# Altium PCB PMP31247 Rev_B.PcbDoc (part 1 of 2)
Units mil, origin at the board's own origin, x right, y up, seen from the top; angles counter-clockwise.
Board outline 3522.83 x 1490.94 mil, 4 copper layers (Top Layer, GND Plane, Signal Layer, Bottom Layer), stack 70.4 mil thick; 56 components, 24 nets, 121 pads, 112 vias.
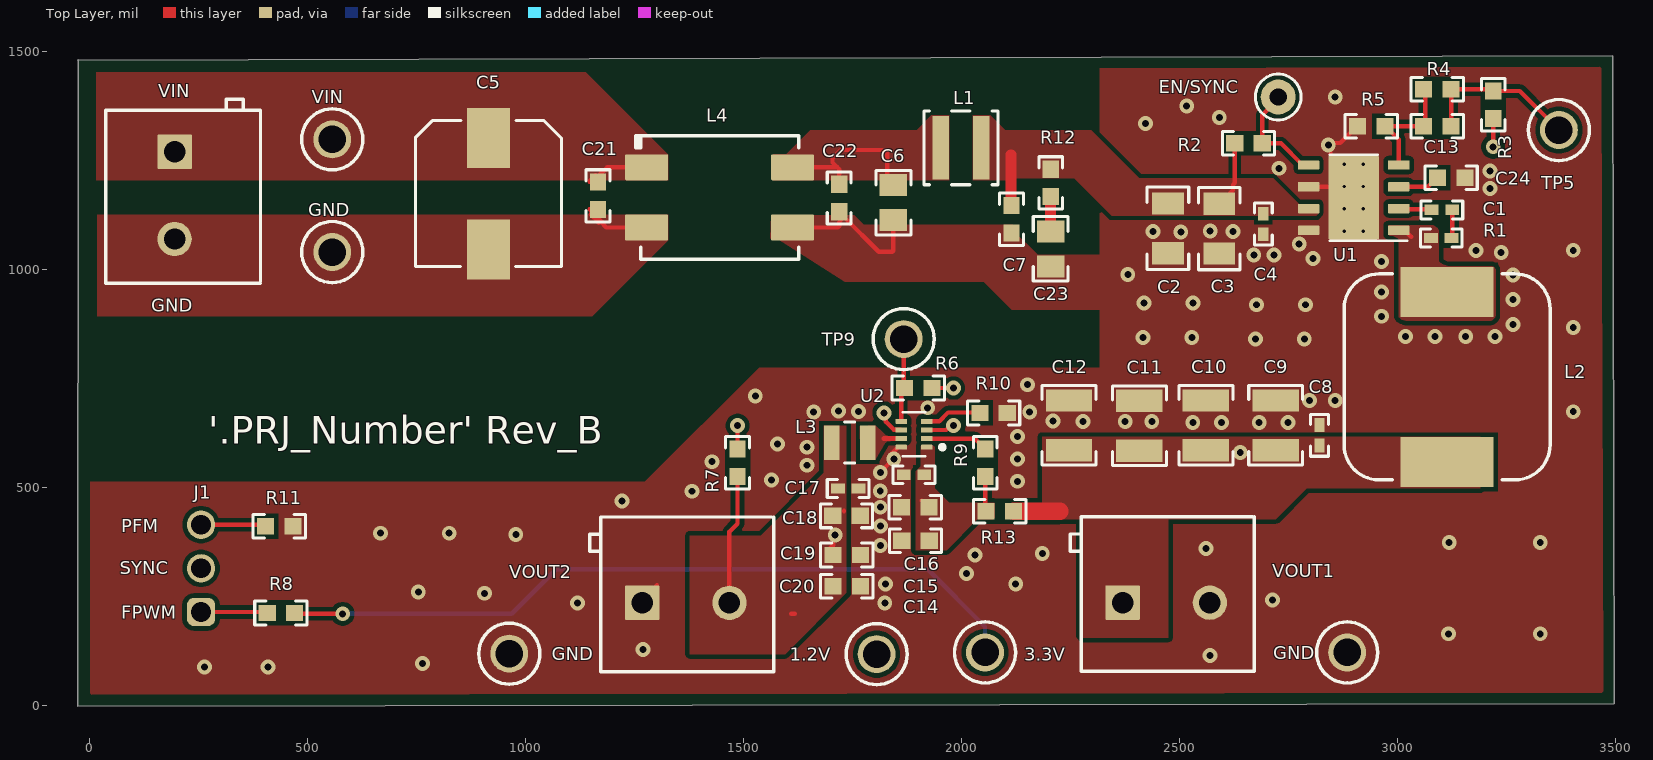
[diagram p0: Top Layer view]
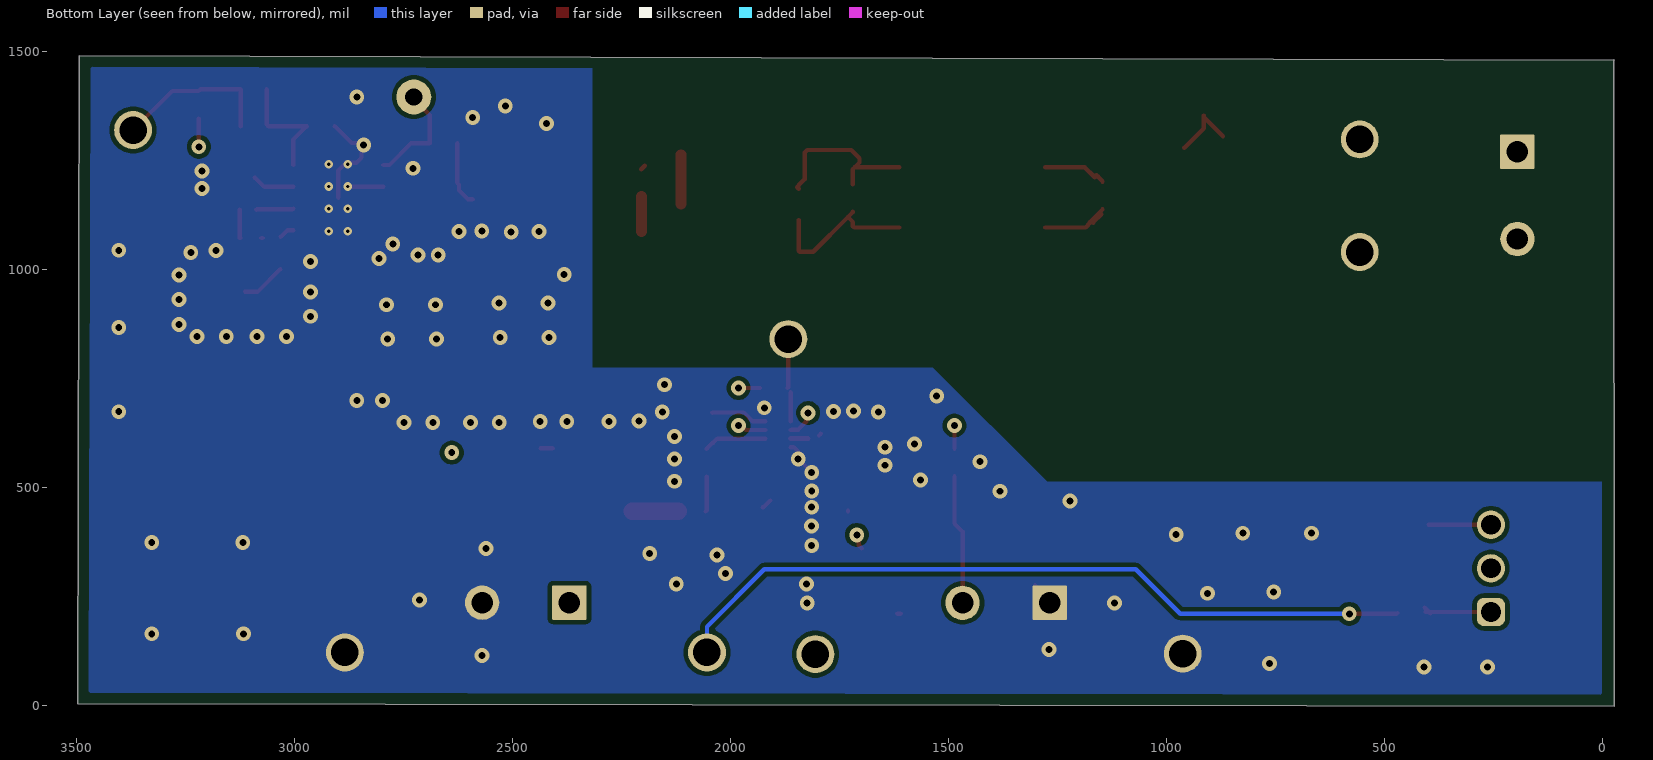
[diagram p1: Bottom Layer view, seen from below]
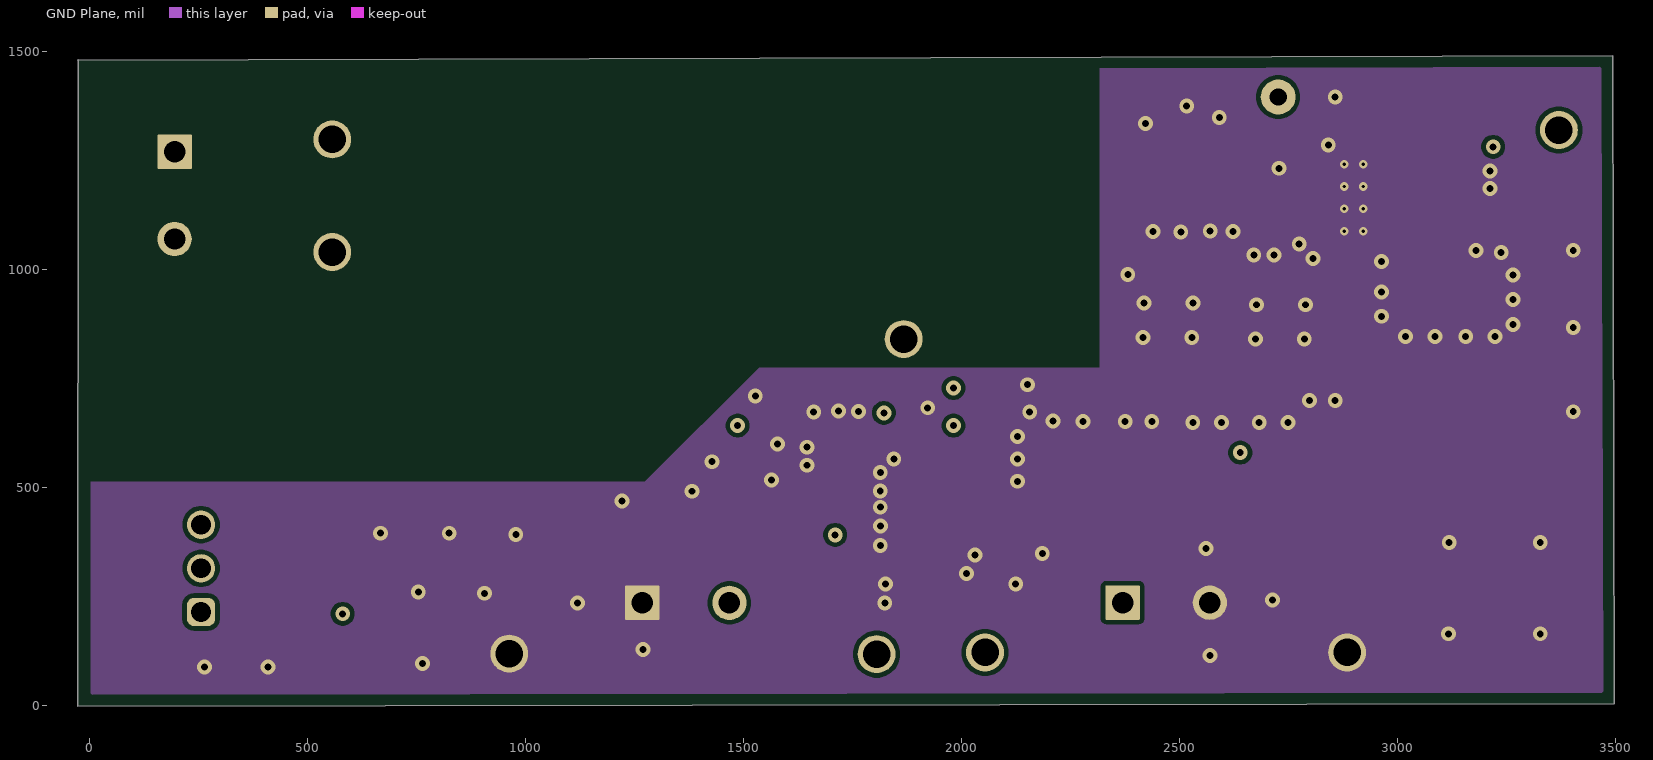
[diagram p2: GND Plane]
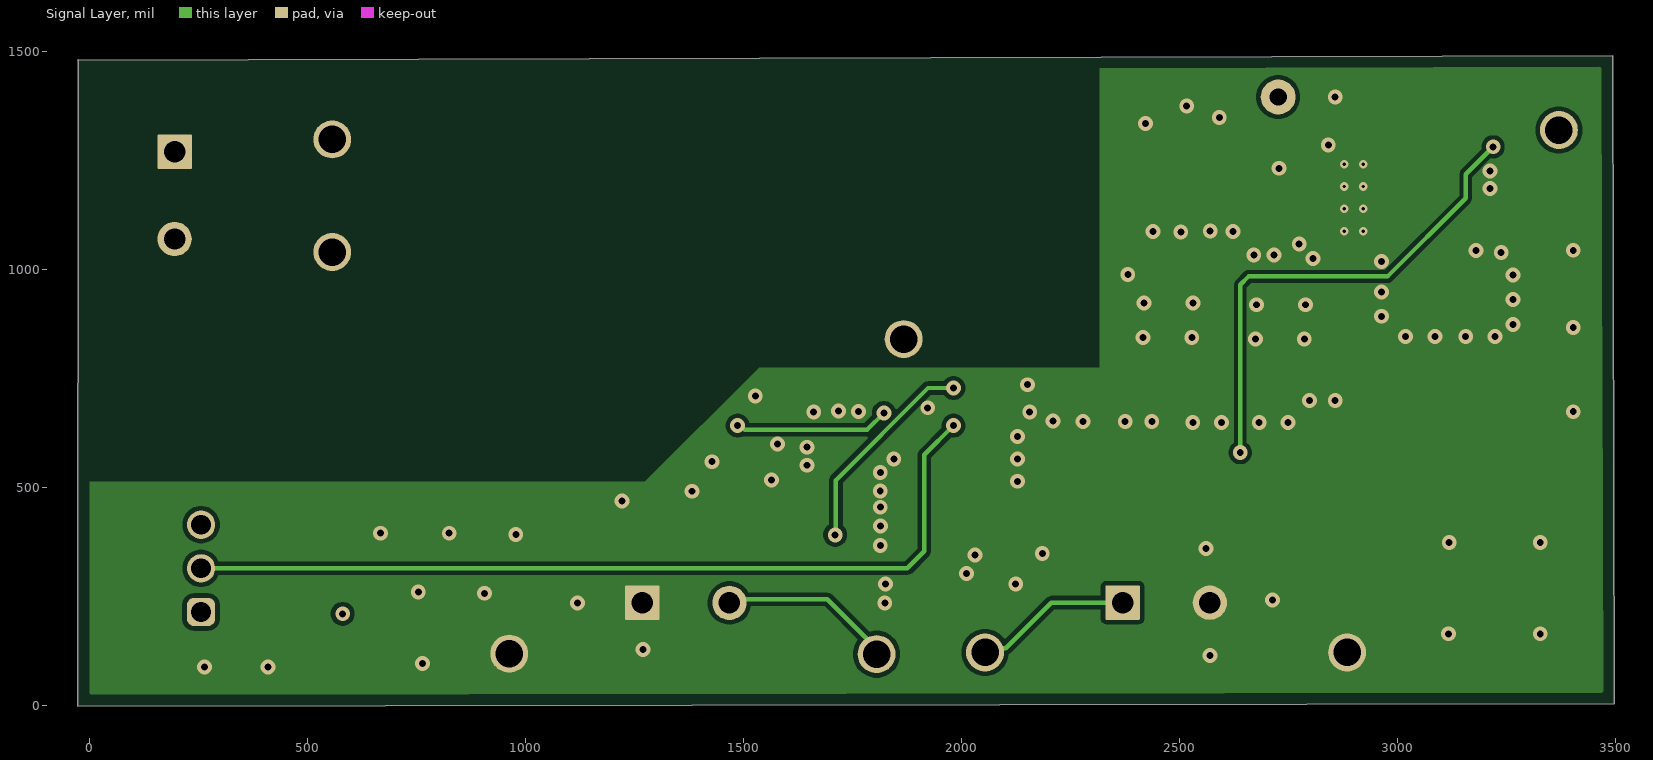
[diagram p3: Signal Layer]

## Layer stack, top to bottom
Top Solder: solder mask 0.4, Solder Resist, Dk 3.5
Top Layer: signal copper 1.4
Dielectric 1: prepreg 2.8, PP-006, Dk 4.1
GND Plane: signal copper 1.4
Dielectric1: dielectric 59.2, FR-4 High Tg, Dk 4.8
Signal Layer: signal copper 1.4
Dielectric 2: prepreg 2.8, PP-006, Dk 4.1
Bottom Layer: signal copper 1.4
Bottom Solder: solder mask 0.4, Solder Resist, Dk 3.5

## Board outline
-26.77,-0.79 -25.98,1481.5 -26.77,1479.92 3492.13,1490.16 3496.06,3.94

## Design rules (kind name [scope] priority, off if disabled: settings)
AcuteAngle [All] p1: minimum=4.50000000000000E+0001 checktracksonly=FALSE
AssemblyTestPointUsage [All] p1: valid=2
BoardOutlineClearance BoardOutlineClearance_MountingHoles [OnCopper and InComponentClass('Mounting Holes')] p1: gap=39.37 ignorepadtopadclearanceinfootprint=FALSE
BoardOutlineClearance BoardOutlineClearance_Poly [OnCopper and IsPoly] p2: gap=25 ignorepadtopadclearanceinfootprint=FALSE
BoardOutlineClearance [OnCopper and Not InComponentClass('Logo') and not InComponentClass('FiducialMark') and not InRegion(1000,500,4000,800) and not InPoly] p3: gap=40 ignorepadtopadclearanceinfootprint=FALSE
Clearance Clearance_Keepouts [((IsTrack Or IsArc) And Not InPoly) And IsFree and IsKeepOut vs ((IsTrack Or IsArc) And Not InPoly) And IsFree and IsKeepOut] p1: gap=0 ignorepadtopadclearanceinfootprint=FALSE
Clearance Clearance_Poly [InPolygon] p2: gap=10 ignorepadtopadclearanceinfootprint=TRUE
Clearance Clearance_FiducialMark [IsKeepOut and InComponentClass('FiducialMark') vs IsPad and InComponentClass('FiducialMark')] p3: gap=0 ignorepadtopadclearanceinfootprint=FALSE
Clearance [All] p4: gap=7.87 ignorepadtopadclearanceinfootprint=TRUE
ComponentClearance ComponentClearance_MountingHoles_FiducialMarks [InComponentClass('Mounting Holes') vs InComponentClass('FiducialMark')] p1: gap=50 collisioncheckmode=3 verticalgap=10 showdistances=FALSE
ComponentClearance ComponentClearance_Shunt [InComponentClass('Header') vs InComponentClass('Shunt')] p2: gap=0 collisioncheckmode=3 verticalgap=0 showdistances=FALSE
ComponentClearance ComponentClearance_Logo [InComponentClass('Logo')] p3: gap=30 collisioncheckmode=3 verticalgap=10 showdistances=FALSE
ComponentClearance ComponentClearance_ScrewToNut [(HasFootprint('NY PMS 440 0025 PH')) vs (HasFootprint('Keystone_1902C'))] p4: gap=5 collisioncheckmode=3 verticalgap=10 showdistances=FALSE
ComponentClearance ComponentClearance_MountingHoles [InComponentClass('Mounting Holes')] p5: gap=100 collisioncheckmode=3 verticalgap=100000 showdistances=FALSE
ComponentClearance ComponentClearance_SmallPassives [HasFootprint('0201*') or HasFootprint('0402*') or HasFootprint('0508') or HasFootprint('0603*') or HasFootprint('0612') or HasFootprint('0805*') or HasFootprint('0815*') or HasFootprint('0830*') or HasFootprint('1206*') or HasFootprint('1210*') or HasFootprint('1808*') or HasFootprint('1812*') or HasFootprint('1825*') or HasFootprint('2010*') or HasFootprint('2220*') or HasFootprint('2225*') or HasFootprint('2512*') or HasFootprint('2728*') or HasFootprint('3518*') vs HasFootprint('0201*') or HasFootprint('0402*') or HasFootprint('0508') or HasFootprint('0603*') or HasFootprint('0612') or HasFootprint('0805*') or HasFootprint('0815*') or HasFootprint('0830*') or HasFootprint('1206*') or HasFootprint('1210*') or HasFootprint('1808*') or HasFootprint('1812*') or HasFootprint('1825*') or HasFootprint('2010*') or HasFootprint('2220*') or HasFootprint('2225*') or HasFootprint('2512*') or HasFootprint('2728*') or HasFootprint('3518*')] p6: gap=14.96 collisioncheckmode=3 verticalgap=10 showdistances=FALSE
ComponentClearance ComponentClearance_THtoSMT [IsThruComponent vs IsSMTComponent] p7: gap=30 collisioncheckmode=3 verticalgap=30 showdistances=FALSE
ComponentClearance ComponentClearance_THtoTH [IsThruComponent vs IsThruComponent] p8: gap=20 collisioncheckmode=3 verticalgap=30 showdistances=FALSE
ComponentClearance [All] p9: gap=20 collisioncheckmode=3 verticalgap=10 showdistances=FALSE
DiffPairsRouting [All] p1: maxlimit=100 minlimit=10 mostfreqgap=10 toplayer_minwidth=15 toplayer_maxwidth=15 toplayer_prefwidth=15 midlayer1_minwidth=15 midlayer1_maxwidth=15 midlayer1_prefwidth=15 midlayer2_minwidth=15 midlayer2_maxwidth=15 midlayer2_prefwidth=15 bottomlayer_minwidth=15 bottomlayer_maxwidth=15 bottomlayer_prefwidth=15 maxuncoupledlength=1000
FabricationTestPointUsage TestPointUsage [All] p1: valid=2 allowmultiple=FALSE
FabricationTestpoint Testpoint [All] p1: side=3 testpointundercomponent=TRUE minsize=40 maxsize=100 preferedsize=60 minholesize=0 maxholesize=40 preferedholesize=32 testpointgrid=1 allowsidetop=TRUE allowsidebottom=TRUE usegrid=TRUE gridtolerance=0.01
FanoutControl Fanout_LCC [IsLCC] p1: bgadir=Out bgaviamode=Centered fanoutstyle=Auto fanoutdirection=Alternating viagrid=1 // Fanout_LCC (Default Rule)
FanoutControl Fanout_BGA [IsBGA] p2: bgadir=Out bgaviamode=Centered fanoutstyle=Auto fanoutdirection=Alternating viagrid=1 // Fanout_BGA (Default Rule)
FanoutControl Fanout_Default [All] p4: bgadir=Out bgaviamode=Centered fanoutstyle=Auto fanoutdirection=Alternating viagrid=1 // Fanout_Default (Default Rule)
FanoutControl Fanout_Small [(CompPinCount < 5)] p5: bgadir=Out bgaviamode=Centered fanoutstyle=Auto fanoutdirection=OutThenIn viagrid=1 // Fanout_Small (Default Rule)
HoleSize [All] p1: absolutevalues=TRUE maxlimit=251 minlimit=7.87 maxpercent=80.000 minpercent=20.000
MinimumAnnularRing MinimumAnnularRing_ThermalPadVias [IsVia and InAnyComponent] p1: minimumring=5.91
MinimumAnnularRing [All] p2: minimumring=7.87
MinimumSolderMaskSliver MinimumSolderMaskSliver_Logo [InComponentClass('Logo') vs InComponentClass('Logo')] p1: minsoldermaskwidth=0.7
MinimumSolderMaskSliver [All] p2: minsoldermaskwidth=3.94
PlaneConnect [All] p1: planeconnectstyle=Relief reliefexpansion=10 reliefentries=4 reliefconductorwidth=10 reliefairgap=10
PolygonConnect [All] p1: connectstyle=Direct reliefconductorwidth=10 reliefentries=4 polygonreliefangle="90 Angle" airgapwidth=10
RoutingLayers [All] p1: top layer_v5=TRUE mid layer 1_v5=FALSE mid layer 2_v5=FALSE bottom layer_v5=TRUE
RoutingVias ThermalPadVias [IsVia and InAnyComponent] p1: holewidth=7.87 width=19.68 viastyle="Through Hole" minholewidth=7.87 minwidth=19.68 maxholewidth=12.99 maxwidth=23.62
RoutingVias [All] p2: holewidth=16 width=34 viastyle="Through Hole" minholewidth=7.87 minwidth=24 maxholewidth=40 maxwidth=65
SilkToSilkClearance SilkToSilkClearance_Pb-FreeLogo [(HasFootprint('Pb-Free_Overlay_Medium') OR HasFootprint('Pb-Free_Overlay_Small')) vs (HasFootprint('Pb-Free_Overlay_Medium') OR HasFootprint('Pb-Free_Overlay_Small'))] p1: silktosilkclearance=0
SilkToSilkClearance [All] p2: silktosilkclearance=3.94
SilkToSolderMaskClearance SilkToComponentPadClearance [(IsPad or IsFill or IsRegion) and InAnycomponent] p1: minsilkscreentomaskgap=5 clearancetoexposedcopper=TRUE
SilkToSolderMaskClearance "Silk to Solder Mask Opening" [All] p2: minsilkscreentomaskgap=3.94 clearancetoexposedcopper=FALSE
SolderMaskExpansion [All] p1: expansion=1.97 istentingtop=FALSE
UnRoutedNet [All] p1: checkbadconnections=TRUE
Width [All] p1: maxlimit=100 minlimit=6 preferedwidth=10
14 further rules are at their usual default settings.

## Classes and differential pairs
component class Header: J1

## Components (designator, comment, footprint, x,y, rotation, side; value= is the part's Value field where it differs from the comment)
1.2V "5010" Keystone5010 1804.86,118.11 r0 top (schematic designator TP7)
3.3V "5010" Keystone5010 2053.4,122.05 r0 top (schematic designator TP3)
C1 "CGA2B3X7R1H104K050BD" 0402 3100.79,1136.81 r0 top value=0.1uF
C2 "CGA5L1X7R1H106K160AE" 1206 2472.83,1094.55 r270 top value=10uF
C3 "CGA5L1X7R1H106K160AE" 1206 2590.55,1094.08 r270 top value=10uF
C4 "CGA2B3X7R1H104K050BD" 0402 2691.47,1104.33 r270 top value=0.1uF
C5 "EEHZC1H680P" SM_RADIAL_8MM 914.57,1174.02 r270 top value=68uF
C6 "GCJ21BR71H105MA01L" 0805_HV 1843.31,1153.54 r270 top value=1uF
C7 "GCM188R71H104KA57D" 0603 2114.17,1115.16 r270 top value=0.1uF
C8 "GCM155R71C104JA55D" 0402 2820.18,619.95 r90 top value=0.1uF
C9 "GRM32ED71A476ME15L" 1210_270 2719.81,642.56 r90 top
C10 "GRM32ED71A476ME15L" 1210_270 2559.84,642.56 r90 top
C11 "GRM32ED71A476ME15L" 1210_270 2407.27,641.97 r90 top
C12 "GRM32ED71A476ME15L" 1210_270 2246.06,642.56 r90 top
C13 "CGA3E2C0G1H470J080AA" 0603 3090.55,1328.74 r180 top value=47pF
C14 "GRM188Z71A106MA73D" 0603 1894.09,378.35 r180 top value=10uF
C15 "GRM188Z71A106MA73D" 0603 1893.31,455.12 r180 top value=10uF
C16 "CGA2B3X7R1H104K050BD" 0402 1890.59,529.53 r180 top value=0.1uF
C17 "CGA2B3X7R1H104K050BD" 0402 1739.69,498.03 r0 top value=0.1uF
C18 "GRM188Z71A106MA73D" 0603 1735.7,435.17 r0 top value=10uF
C19 "GRM188Z71A106MA73D" 0603 1736.22,345.67 r0 top value=10uF
C20 "GRM188Z71A106MA73D" 0603 1736.22,273.62 r0 top value=10uF
C21 "GCM188R71H104KA57D" 0603 1166.14,1168.9 r270 top value=0.1uF
C22 "GCM188R71H104KA57D" 0603 1718.9,1164.17 r270 top value=0.1uF
C23 "GCJ21BR71H105MA01L" 0805_HV 2203.98,1047.24 r270 top value=1uF
C24 "EMK107BB7225KA-T" 0603 3122.05,1210.63 r0 top value=2.2uF
EN/SYNC "5003" Keystone5003 2725.55,1395.67 r90 top
GND "5011" Keystone5011 556.69,1040.16 r90 top (schematic designator TP1)
GND "5011" Keystone5011 962.6,119.29 r0 top (schematic designator TP8)
GND "5011" Keystone5011 2883.66,122.05 r0 top (schematic designator TP6)
J1 "61300311121" WURTH_61300311121 255.91,314.96 r90 top
L1 "XAL4040-103MEB" XAL4040 1998.17,1278.9 r0 top value=10uH
L2 "744770115" WE-PD_1280 3112.79,753.94 r270 top value=15uH
L3 "DFE252012PD-R47M" DFE252012P 1742.88,603.27 r180 top value=470nH
L4 "ACM9070-701-2PL-TL01" TDK_ACM9070 1444.88,1165.35 r0 top
R1 "CRCW04020000Z0ED" 0402 3099.41,1072.27 r0 top value=0
R2 "CRCW06030000Z0EA" 0603 2657.48,1289.37 r0 top value=0
R3 "CRCW06030000Z0EA" 0603 3218.5,1377.95 r270 top value=0
R4 "RC0603FR-0751KL" 0603 3090.55,1413.39 r0 top value=51.0k
R5 "CRCW060322K1FKEA" 0603 2938.98,1328.74 r0 top value=22.1k
R6 "CRCW06030000Z0EA" 0603 1900.39,728.35 r0 top value=0
R7 "CRCW0603100KFKEA" 0603 1486.02,557.31 r270 top value=100k
R8 "CRCW06030000Z0EA" 0603 438.98,212.6 r0 top value=0
R9 "CRCW06030000Z0EA" 0603 2053.94,557.09 r90 top value=0
R10 "CRCW06038K06FKEA" 0603 2073.03,671.26 r180 top value=8.06k
R11 "CRCW06030000Z0EA" 0603 435.04,411.42 r180 top value=0
R12 "CRCW06030000Z0EA" 0603 2203.98,1198.64 r90 top value=0
R13 "CRCW06030000Z0EA" 0603 2087.4,445.94 r180 top value=0
TP5 "5012" Keystone5012 3369.25,1319.88 r0 top
TP9 "5012" Keystone5012 1866.96,840.55 r0 top
U1 "LMR23630AFQDDARQ1" DDA0008E_L 2898.62,1164.76 r180 top
U2 "TPS6285018AQDRLRQ1" DRL0008A-MFG 1890.55,622.28 r180 top
VIN "5010" Keystone5010 556.69,1298.43 r90 top (schematic designator TP2)
VIN "ED120/2DS" On-Shore_ED120_2DS 195.28,1170.08 r270 top
VOUT1 "ED120/2DS" On-Shore_ED120_2DS 2468.9,236.22 r0 top
VOUT2 "ED120/2DS" On-Shore_ED120_2DS 1367.35,235.79 r0 top

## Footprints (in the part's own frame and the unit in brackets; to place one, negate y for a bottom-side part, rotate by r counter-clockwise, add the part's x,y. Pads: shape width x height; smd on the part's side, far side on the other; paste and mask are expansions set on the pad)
0402 [mm] "0402 from SM-752 data"
  rect 0.8x0.6 smd: 1(-0.6,0) 2(0.6,0)
  silkscreen extent -1.22,-0.52 1.22,0.52, body extent -0.55,-0.3 0.55,0.3, height 0.6
0603 [mm] "0603 from SM-752 data"
  rect 1x0.95 smd: 1(-0.8,0) 2(0.8,0)
  silkscreen extent -1.52,-0.69 1.52,0.69, body extent -0.87,-0.47 0.87,0.47, height 1
0805_HV [mil] "0805 with 30mil clearance between pads"
  rect 50x63 smd: 1(-40,0) 2(40,0)
  silkscreen extent -74,-40 74,40, body extent -43,-29 43,29, height 57
1206 [mm] "1206 from SM-752 data"
  rect 1.3x1.85 smd: 1(-1.45,0) 2(1.45,0)
  silkscreen extent -2.4,-1.21 2.4,1.21, body extent -1.7,-0.9 1.7,0.9, height 1.35
1210_270 [mm] "1210"
  rect 1.3x2.7 smd: 1(-1.45,0) 2(1.45,0)
  silkscreen extent -2.32,-1.57 2.32,1.57, body extent -1.7,-1.35 1.7,1.35, height 2.7
DDA0008E_L [mm]
  rrect18% 1.25x0.55 smd: 1(-2.625,1.905) 2(-2.625,0.635) 3(-2.625,-0.635) 4(-2.625,-1.905) 5(2.625,-1.905) 6(2.625,-0.635) 7(2.625,0.635) 8(2.625,1.905)
  rrect7% 2.95x4.9 smd paste-1.5 mask-1.5: 9(0,0)
  rrect4% 2.4x3.1 on Top Solder: 9(0,0)
  rrect4% 2.4x3.1 on Top Paste: 9(0,0)
  silkscreen extent -3.13,-2.5 1.4,2.5, body extent -3,-2.45 3,2.45, height 1.57
DFE252012P [mm] "TOKO, Pad sizes increased as per request"
  rect 0.9x2 smd: 1(-1.05,0) 2(1.05,0)
  silkscreen extent -0.3,-1.2 0.3,1.2, body extent -1.35,-1.1 1.35,1.1, height 1.2
DRL0008A-MFG [mm]
  rrect33% 0.67x0.3 smd paste+0 mask+0: 1(-0.74,0.75) 2(-0.74,0.25) 3(-0.74,-0.25) 4(-0.74,-0.75) 5(0.74,-0.75) 6(0.74,-0.25) 7(0.74,0.25) 8(0.74,0.75)
  silkscreen extent -1.78,-1.28 0.65,1.28, body extent -1.17,-1.35 1.17,1.35, height 0.25
Keystone5003 [mil] "For Keystone 500x miniature loop terminals"
  round 80 hole 40: 1(0,0)
  silkscreen extent -52,-52 52,52, body extent -49,-49 49,49, height 182
Keystone5010 [mil] "Keystone Multipurpose loops"
  round 87 hole 63: 1(0,0)
  silkscreen extent -70,-70 70,70, body extent -63,-63 63,62, height 319
Keystone5011 [mil] "Keystone Multipurpose loops"
  round 87 hole 63: 1(0,0)
  silkscreen extent -70,-70 70,70, body extent -63,-63 63,62, height 319
Keystone5012 [mil] "Keystone Multipurpose loops"
  round 87 hole 63: 1(0,0)
  silkscreen extent -70,-70 70,70, body extent -63,-63 63,62, height 319
On-Shore_ED120_2DS [mm] "ONSHORE"
  rrect5% 2x2 hole 1.25: 1(-2.54,0)
  round 2 hole 1.25: 2(2.54,0)
  silkscreen extent -5.6,-4 5.12,5, body extent -5.78,-4 5.08,5, height 13
SM_RADIAL_8MM [mm] "Nichicon 8x10"
  rect 3.5x2.5 smd: 1(-3.25,0) 2(3.25,0)
  silkscreen extent -4.25,-4.25 4.25,4.25, body extent -4.25,-4.25 4.25,4.25, height 10.5
TDK_ACM9070 [mm] "SMD, 4-Leads, Body 9x7mm"
  rrect7% 2.5x1.5 smd: 1(-4.25,1.75) 2(-4.25,-1.75) 3(4.25,-1.75) 4(4.25,1.75)
  silkscreen extent -4.87,-3.6 4.6,3.6, body extent -4.6,-3.6 4.6,3.6, height 4.5
WE-PD_1280 [mm] "Wurth Elektronik recommended land pattern"
  rect 2.9x5.4 smd: 1(-4.95,0) 2(4.95,0)
  silkscreen extent -6,-6 6,6, body extent -6,-6 6,6, height 8.01
WURTH_61300311121 [mm] "Header, 2.54mm, 3x1, TH"
  rrect50% 1.65x1.65 hole 1.15: 1(-2.54,0)
  round 1.65 hole 1.15: 2(0,0) 3(2.54,0)
  body extent -3.81,-1.27 3.81,1.27, height 8.54
XAL4040 [mil] "Coilcraft XAL4040 7/18/12"
  rect 38x146 smd: 1(-46.5,0) 2(46.5,0)
  silkscreen extent -84,-84 84,84, body extent -84,-84 84,84, height 161

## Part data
1.2V 3.3V VIN: library part CMP-0055147-1, "Test Point, Multipurpose, Red, TH", Color=Red, Manufacturer=Keystone, Supplier Part Number 1=36-5010-ND
C1 C4 C16 C17: library part CMP-0084548-1, "CAP, CERM, 0.1 µF, 50 V,+/- 10%, X7R, AEC-Q200 Grade 1, 0402", Cap_Case=0402, Manufacturer=TDK, TempCo=X7R, Tolerance_%=10%, Value2=50V, ValueDisplayed=0.1µF
C2 C3: library part CMP-0860898-1, "CAP, CERM, 10 µF, 50 V,+/- 10%, X7R, AEC-Q200 Grade 1, 1206", Cap_Case=1206, Manufacturer=TDK, TempCo=X7R, Tolerance_%=10%, Value2=50V, ValueDisplayed=10µF
C5: library part CMP-0012599-3, "CAP, Polymer Hybrid, 68 uF, 50 V, +/- 20%, 30 ohm, 8x10 SMD", Manufacturer=Panasonic, Supplier Part Number 1=P15465CT-ND, Tolerance_%=20%, Value1="30 ohm", Value2=50V, ValueDisplayed=68uF
C6 C23: library part CMP-0080480-1, "CAP, CERM, 1 µF, 50 V,+/- 20%, X7R, AEC-Q200 Grade 1, 0805", Cap_Case=0805, Manufacturer=MuRata, Supplier Part Number 1=490-16470-1-ND, TempCo=X7R, Tolerance_%=20%, Value2=50V, ValueDisplayed=1µF
C7 C21 C22: library part CMP-0007144-4, "CAP, CERM, 0.1 uF, 50 V, +/- 10%, X7R, 0603", Cap_Case=0603, Manufacturer=MuRata, Supplier Part Number 1=490-4779-1-ND, TempCo=X7R, Tolerance_%=10%, Value1="0.02 ohm", Value2=50V, ValueDisplayed=0.1uF
C8: library part CMP-0080702-1, "CAP, CERM, 0.1 µF, 16 V,+/- 5%, X7R, AEC-Q200 Grade 1, 0402", Cap_Case=0402, Manufacturer=MuRata, Supplier Part Number 1=490-16433-1-ND, TempCo=X7R, Tolerance_%=5%, Value2=16V, ValueDisplayed=0.1µF
C9 C10 C11 C12: library part CMP-0086480-2, "47µF ±20% 10V Ceramic Capacitor X7T 1210 (3225 Metric)", Manufacturer=Murata, TempCo=+22-33%, Tolerance_%=20%
C13: library part CMP-0007073-4, "CAP, CERM, 47 pF, 50 V, +/- 5%, C0G/NP0, AEC-Q200 Grade 1, 0603", Cap_Case=0603, Manufacturer=TDK, Supplier Part Number 1=445-5636-1-ND, TempCo=C0G/NP0, Tolerance_%=5%, Value1=Unknown, Value2=50V, ValueDisplayed=47pF
C14 C15 C18 C19 C20: library part CMP-0007497-5, "CAP, CERM, 10 uF, 10 V, +/- 20%, X7R, 0603", Cap_Case=0603, Manufacturer=MuRata, Supplier Part Number 1=81-GRM188Z71A106MA3D, TempCo=X7R, Tolerance_%=20%, Value1=Unknown, Value2=10V, ValueDisplayed=10uF
C24: library part CMP-0007121-4, "CAP, CERM, 2.2 uF, 16 V, +/- 10%, X7R, 0603", Cap_Case=0603, Manufacturer="Taiyo Yuden", Supplier Part Number 1=EMK107BB7225KA-T-ND, TempCo=X7R, Tolerance_%=10%, Value1=Unknown, Value2=16V, ValueDisplayed=2.2uF
EN/SYNC: library part CMP-0055140-2, "Test Point, Miniature, Orange, TH", Color=Orange, Manufacturer="Keystone Electronics", Supplier Part Number 1=36-5003-ND
GND GND GND: library part CMP-0055148-1, "Test Point, Multipurpose, Black, TH", Color=Black, Manufacturer=Keystone, Supplier Part Number 1=36-5011-ND
J1: library part CMP-0054796-2, "Header, 2.54 mm, 3x1, Gold, TH", Color=Black, Manufacturer="Wurth Elektronik", Supplier Part Number 1=732-5316-ND
L1: library part CMP-0060992-1, "Inductor, Shielded, Composite, 10 uH, 3 A, 0.084 ohm, SMD", Manufacturer=Coilcraft, Supplier Part Number 1=994-XAL4040-103MEB, Value1="0.084 ohm", Value2=3A, ValueDisplayed=TBD
L2: library part CMP-0064525-2, "Inductor, Shielded Drum Core, Ferrite, 15 uH, 5 A, 0.024 ohm, SMD", Manufacturer="Wurth Elektronik", Supplier Part Number 1=732-1225-1-ND, Value1="0.024 ohm", Value2=5A, ValueDisplayed=15uH
L3: library part CMP-0058944-1, "Inductor, Shielded, 470 nH, 4.7 A, 0.021 ohm, SMD", Manufacturer="MuRata Toko", Value1="0.021 ohm", Value2=4.7A, ValueDisplayed=470nH
L4: library part CMP-0013076-3, "Coupled inductor, 5 A, 0.01 ohm, SMD", Manufacturer=TDK, Supplier Part Number 1=445-2216-1-ND
R1: library part CMP-0026822-1, "RES, 0, 5%, 0.063 W, 0402", Manufacturer=Vishay-Dale, Power_W=63mW, Supplier Part Number 1=541-0.0JCT-ND, TempCo="200 ppm/C", Tolerance_%=5%, Value2=0.063W, Value_Code=0000, ValueDisplayed=0
R2 R3 R6 R8 R9 R11 R12 R13: library part CMP-0025697-2, "RES, 0, 5%, 0.1 W, 0603", Manufacturer=Vishay-Dale, Power_W=100mW, Supplier Part Number 1=541-0.0GCT-ND, TempCo="200 ppm/C", Tolerance_%=5%, Value2=0.1W, Value_Code=0000, ValueDisplayed=0
R4: library part CMP-0023167-5, "RES, 51.0 k, 1%, 0.1 W, 0603", Manufacturer=Yageo, Power_W=100mW, Supplier Part Number 1=311-51.0KHRCT-ND, TempCo="100 ppm/C", Tolerance_%=1%, Value2=0.1W, Value_Code=51k0, ValueDisplayed=51.0k
R5: library part CMP-0022220-4, "RES, 22.1 k, 1%, 0.1 W, AEC-Q200 Grade 0, 0603", Manufacturer=Vishay-Dale, Power_W=100mW, Supplier Part Number 1=541-22.1KHCT-ND, TempCo="100 ppm/C", Tolerance_%=1%, Value2=0.1W, Value_Code=22k1, ValueDisplayed=22.1k
R7: library part CMP-0021990-4, "RES, 100 k, 1%, 0.1 W, AEC-Q200 Grade 0, 0603", Manufacturer=Vishay-Dale, Power_W=100mW, Supplier Part Number 1=541-100KHCT-ND, TempCo="100 ppm/C", Tolerance_%=1%, Value2=0.1W, Value_Code=100k
R10: library part CMP-0022634-4, "RES, 8.06 k, 1%, 0.1 W, AEC-Q200 Grade 0, 0603", Manufacturer=Vishay-Dale, Power_W=100mW, Supplier Part Number 1=541-8.06KHCT-ND, TempCo="100 ppm/C", Tolerance_%=1%, Value2=0.1W, Value_Code=8k06, ValueDisplayed=8.06k
TP5 TP9: library part CMP-0055149-2, "Test Point, Multipurpose, White, TH", Color=White, Manufacturer="Keystone Electronics", Supplier Part Number 1=36-5012-ND
U1: library part CMP-0013268-3, "SIMPLE SWITCHER, 36V, 3A Synchronous Step-Down Converter, DDA0008E (SOIC-8)", Alternate Manufacturer="Texas Instruments", Alternate PartNumber=LMR23630AFQDDAQ1
U2: library part CMP-0092216-2, "1.2V fixed voltage Step-Down Converter", Manufacturer="Texas Instruments", Max Supply Voltage=6V, Min Supply Voltage=2.7V, Nominal Supply Current=17uA, Operating Temperature Range="-40°C to +150°C", Output Voltage=1.2V, Switching Frequency=1.8-4MHz
VIN VOUT1 VOUT2: library part CMP-0074910-1, "Terminal Block, 5.08 mm, 2x1, Brass, TH", Color=Blue, Current_A=15A, Manufacturer="On-Shore Technology", Supplier Part Number 1=ED1609-ND, Voltage_V=300V

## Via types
v1: diameter 34, hole 16, Top Layer to Bottom Layer, tented both sides, 104 vias
v2: diameter 19.68, hole 7.87, Top Layer to Bottom Layer, 4 vias
v3: diameter 19.68, hole 7.87, Top Layer to Bottom Layer, tented both sides, 4 vias

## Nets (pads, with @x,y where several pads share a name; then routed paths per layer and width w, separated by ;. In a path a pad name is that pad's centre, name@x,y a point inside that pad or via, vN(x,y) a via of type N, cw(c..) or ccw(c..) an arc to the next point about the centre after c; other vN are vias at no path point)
3V3: 3.3V.1 C8.1 C9.1 C10.1 C11.1 C12.1 L2.2 R3.2 R8.2 R13.1 VOUT1.1 | length 3429.3
  Top Layer w10: R8.2@470.47,212.6 472.44,210.63 v1(580.71,210.63) ; C11.1@2407.27,590.4 C11.1@2434.83,590.4 ; v1(3218.5,1281.5) R3.2@3218.5,1346.46
  Top Layer w39.37: R13.1@2118.9,445.94 2225.2,445.94
  Signal Layer w10: 3.3V.1@2053.4,122.05 2063.08,131.73 2101.02,131.73 2205.51,236.22 VOUT1.1@2368.9,236.22 ; v1(2638.58,580.31) 2638.58,965.15 2657.69,984.25 2976.38,984.25 3155.51,1163.39 3155.51,1218.5 v1(3218.5,1281.5)
  Bottom Layer w10: v1(580.71,210.63) 968.5,210.63 1070.47,312.6 1922.05,312.6 2053.4,181.24 3.3V.1@2053.4,122.05
GND: C2.2 C3.2 C4.2 C6.2 C7.2 C8.2 C9.2 C10.2 C11.2 C12.2 C14.2 C15.2 C16.2 C17.2 C18.2 C19.2 C20.2 C22.2 C23.2 C24.2 GND.1@962.6,119.29 GND.1@2883.66,122.05 L4.3 R5.1 R10.1 R11.1 U1.6 U1.8 U1.9@2898.62,1164.76 U2.8 VOUT1.2 VOUT2.1 | length 821.6
  Top Layer w10: VOUT2.1@1268.9,244.09 1301.3,276.5 ; L4.3@1612.2,1096.46 1715.87,1096.46 1718.78,1099.37 1718.78,1108.83 C22.2@1730.27,1120.32 ; C22.2@1718.9,1132.68 1718.9,1131.69 C22.2@1730.27,1120.32 ; v1(1813.32,534.48) 1813.32,534.88 1835.74,557.31 1835.74,574.37 1854.13,592.76 U2.8@1861.42,592.76 ; C6.2@1843.31,1113.54 1843.31,1043.32 1841.02,1041.03 1809.56,1041.03 C22.2@1730.27,1120.32 ; U1.6@2795.28,1189.76 2876.38,1189.76 v2(2876.97,1190.35) ; U1.9@2898.62,1164.76 2898.62,1227.36 2880.71,1245.28 2856.5,1245.28 2845.55,1256.22 2845.55,1273.94 2840.55,1278.94 v1(2840.55,1285.43) 2845.14,1290.03 2867.78,1290.03 2906.5,1328.74 R5.1@2907.48,1328.74
  other v1: 263.78,88.58 409.41,88.58 763.78,96.46 2568.9,115 1268.9,129.09 3115.95,164.86 3326.44,164.86 1118.9,235.79 1823.53,235.79 2712.8,242.13 905.51,257.67 754.05,260.62 1825.51,278.7 2123.82,278.7 2010.59,303.16 2030.44,345.38 2184.8,349.21 2559.84,360.67 1813.32,367.2 3117.6,374.02 3326.44,374.02 977.56,392.52 667.32,395.5 824.8,395.5 1813.9,411.93 1813.32,455.12 1221.26,469.29 1381.48,491.69 1813.18,491.95 2127.5,514.56 1563.79,517.72 1645.58,551.28 1427.56,559.45 1844.19,565.92 2127.72,565.96 1645.58,592.76 1577.27,599.86 2127.72,616.92 2529.82,649.52 2595.82,649.52 2682.05,649.52 2748.05,649.52 2209.45,652.64 2278.35,651.73 2374.8,651.73 2435.83,651.73 1660.55,673.63 2155.91,673.23 3402.1,674.08 1763.31,674.81 1717.64,676 1922.05,683 2797.48,699.65 2856.3,699.65 1526.72,710.2 2150.94,735.98 2673.23,840.55 2785.43,840.55 2415.35,844.49 2527.56,844.49 3017.72,846.46 3085.1,846.46 3155.51,846.46 3222.89,846.46 3402.1,867 3263.78,873.73 2962.6,892.84 2675.73,919.29 2787.93,919.29 2417.86,923.23 2530.06,923.23 3263.78,931.1 2962.6,948.82 3263.78,987.67 2380.82,988.97 2962.6,1018.76 2805.12,1025.59 2669.66,1033.46 2716.13,1033.46 3236.9,1039.46 3179.13,1043.31 3402.1,1044.16 2773.83,1058.46 2502.36,1086.26 2438.58,1087.4 2621.97,1087.4 2569.68,1088.58 3211.29,1186.2 3211.29,1226.22 2727.68,1232.15 2421.26,1334.65 2590.55,1348.29 2515.75,1374.76 2856.3,1395.67
  other v2: 2876.97,1139.17 2920.28,1139.17 2920.28,1190.35
  other v3: 2876.97,1087.99 2920.28,1087.99 2876.97,1241.54 2920.28,1241.54
GNDA: C5.2 C21.2 GND.1@556.69,1040.16 L4.2 VIN.2 | length 220.3
  Top Layer w10: 1146.46,1138.58 1146.46,1137.6 1175.98,1108.07 C21.2@1156.89,1127.17 ; C21.2@1149.02,1126.77 1168.11,1107.68 ; C21.2@1163.78,1118.7 1179.13,1103.35 1179.13,1102.31 1184.99,1096.46 L4.2@1277.56,1096.46
MODE/SYNC: J1.2 U2.3 | length 2056.2
  Top Layer w10: U2.3@1919.69,632.13 1964.42,632.13 1974.61,642.31 v1(1981.1,642.31)
  Signal Layer w10: J1.2@255.91,314.96 1875.2,314.96 1914.13,353.89 1914.13,575.34 v1(1981.1,642.31)
Net1.2V_1: 1.2V.1 C17.1 C18.1 C19.1 C20.1 L3.2 R6.2 R7.2 VOUT2.2 | length 1263.9
  Top Layer w10: VOUT2.2@1467.35,235.79 1467.35,398.57 1486.02,417.24 R7.2@1486.02,525.81 ; 1609.06,210.63 1616.93,210.63 ; C19.1@1698.7,361.3 1705.24,367.84 1705.24,387.15 v1(1709.83,391.74) ; 1730.2,445.94 1730.2,446.93 ; R6.2@1931.89,728.35 v1(1981.1,728.35)
  Signal Layer w10: VOUT2.2@1468.9,244.09 1691.73,244.09 1.2V.1@1809.84,125.98 ; v1(1709.83,391.74) 1711.42,393.33 1711.42,517.08 1922.68,728.35 v1(1981.1,728.35)
NetC1_1: C1.1 U1.2 | length 85.9
  Top Layer w10: U1.2@3001.97,1139.76 3003.44,1138.29 3085.14,1138.29 C1.1@3086.61,1136.81
NetC1_2: C1.2 R1.2 | length 65.9
  Top Layer w10: R1.2@3123.03,1072.27 3124.41,1072.27 C1.2@3124.41,1136.81
NetC2_1: C2.1 C3.1 C4.1 C7.1 L1.2 R2.1 R12.2 U1.7 | length 273.4
  Top Layer w10: R12.2@2196.1,1238.01 R12.2@2203.98,1230.14 ; C3.1@2590.55,1161.42 2601.38,1161.42 2621.97,1182.01 2621.97,1194.63 2625.98,1198.64 R2.1@2625.98,1289.37
  Top Layer w25: C7.1@2113.39,1150 2113.39,1263.32
NetC5_1: C5.1 C21.1 L4.1 VIN.1 | length 303.8
  Top Layer w10: C5.1@870.35,1305.51 C5.1@914.57,1349.72 ; C5.1@914.57,1353.15 C5.1@914.57,1349.72 ; C5.1@958.78,1279.41 914.57,1323.62 C5.1@914.57,1349.72 ; 1146.46,1201.57 1146.46,1202.56 C21.1@1160.16,1216.26 ; C21.1@1156.52,1212.62 C21.1@1160.16,1216.26 ; C21.1@1161.14,1216.26 C21.1@1160.16,1216.26 ; C21.1@1164.29,1211.54 1167.93,1215.18 1187.01,1234.25 L4.1@1277.56,1234.25
NetC6_1: C6.1 C22.1 L1.1 L4.4 | length 390.2
  Top Layer w10: L4.4@1612.2,1234.25 1715,1234.25 ; C22.1@1718.9,1195.67 1718.9,1230.35 1715,1234.25 ; C6.1@1843.31,1185.04 C6.1@1846.93,1188.66 ; C6.1@1843.31,1193.54 1829.45,1207.4 1829.45,1268.22 1823.59,1274.08 1722.5,1274.08 1703.75,1255.32 1703.75,1245.5 1715,1234.25
NetC13_1: C13.1 R3.1 R4.2 TP5.1 | length 366.6
  Top Layer w10: C13.1@3122.05,1328.74 R4.2@3122.05,1409.45 ; R4.2@3122.05,1413.39 3214.57,1413.39 R3.1@3218.5,1409.45 3279.68,1409.45 TP5.1@3369.25,1319.88
NetC13_2: C13.2 R4.1 R5.2 U1.4 | length 276.5
  Top Layer w10: R5.2@2970.47,1328.74 R5.2@2971.46,1328.74 ; U1.4@3001.97,1239.76 3001.97,1298.23 R5.2@2971.46,1328.74 ; R4.1@3062.99,1413.39 3062.99,1332.68 C13.2@3059.06,1328.74 R5.2@2971.46,1328.74
NetC14_1: C14.1 C15.1 C16.1 R9.1 R13.2 U2.1 | length 104.2
  Top Layer w10: C15.1@1908.42,470.52 1923.82,455.12 C15.1@1924.8,455.12 C15.1@1925.79,455.12 ; R9.1@2053.94,525.59 2053.94,447.91 R13.2@2055.91,445.94
NetC23_1: C23.1 R12.1 | length 87.4
  Top Layer w10: R12.1@2203.98,1167.15 R12.1@2209.25,1161.87
  Top Layer w25: C23.1@2203.98,1087.24 R12.1@2203.98,1167.15
NetEN/SYNC_1: EN/SYNC.1 R2.2 U1.5 | length 248.3
  Top Layer w10: EN/SYNC.1@2725.55,1395.67 2725.55,1391.04 2688.98,1354.47 R2.2@2688.98,1289.37 2731.89,1289.37 2781.5,1239.76 U1.5@2795.28,1239.76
